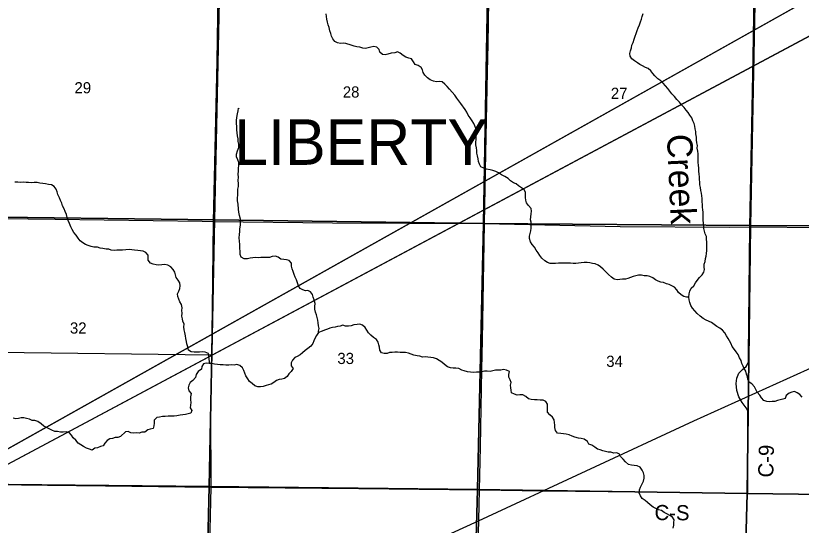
# Model space of a CAD drawing. Extents: x -6.2 to 37.4, y 0.2 to 22.2.
# Drawn here: x 3.568 to 5.038, y 18.286 to 19.239 of the extents above; entities that cross this region are included whole.
import ezdxf

# ---------------------------------------------------------------- set-up
doc = ezdxf.new("R2010")
doc.units = 0
for name, color, linetype in [('GM_X_County_Road', 7, 'Continuous'), ('GM_X_County_Road_Text', 7, 'Continuous'), ('GM_X_Minor_River', 7, 'Continuous'), ('GM_X_Minor_River_Text', 7, 'Continuous'), ('GM_X_Rail_Line', 7, 'Continuous'), ('GM_X_Section', 7, 'Continuous'), ('GM_X_Section_Text', 7, 'Continuous'), ('GM_X_Township_Road', 7, 'Continuous'), ('GM_X_Township_Text', 7, 'Continuous'), ('SH_Border', 7, 'Continuous'), ('SH_Data', 7, 'Continuous')]:
    doc.layers.add(name, color=color, linetype=linetype)

msp = doc.modelspace()

# ---------------------------------------------------------------- linework, layer by layer
at = {"layer": 'GM_X_County_Road'}
for points in [[(4.9421, 18.8443), (4.9484, 19.1615), (4.9514, 19.3541)], [(3.439, 18.8612), (3.6419, 18.8581), (3.9173, 18.8544), (3.9385, 18.8541), (4.161, 18.8513), (4.4458, 18.8505)], [(4.4458, 18.8505), (4.6995, 18.8444), (4.9048, 18.8435), (4.9421, 18.8443), (5.0809, 18.8428)], [(4.9381, 18.3459), (4.9384, 18.4907), (4.9383, 18.4998), (4.9352, 18.5053), (4.9276, 18.5153), (4.9215, 18.5262), (4.9174, 18.538), (4.9165, 18.5513), (4.9178, 18.5608), (4.9215, 18.5704), (4.9282, 18.5772), (4.9351, 18.5831), (4.9392, 18.5905), (4.9394, 18.6039), (4.9421, 18.8443)], [(3.4329, 18.3636), (3.6277, 18.3611), (3.7361, 18.3598), (3.9338, 18.3574), (4.2101, 18.3545), (4.4362, 18.3519), (4.4372, 18.3519)], [(4.4372, 18.3519), (4.5554, 18.3503), (4.7371, 18.3484), (4.9381, 18.3459), (4.9391, 18.3459)], [(4.9391, 18.3459), (5.0653, 18.3443), (5.0669, 18.3443), (5.0809, 18.3441)]]:
    msp.add_lwpolyline(points, dxfattribs=at)
at = {"layer": 'GM_X_Minor_River'}
for points in [[(4.4309, 18.9871), (4.4307, 18.9918), (4.4296, 18.9975), (4.429, 19.0023), (4.4299, 19.0076), (4.43, 19.0132), (4.4299, 19.0184), (4.4298, 19.0231), (4.4293, 19.0281), (4.4275, 19.0328), (4.4256, 19.0376), (4.4226, 19.0424), (4.4188, 19.0476), (4.4149, 19.0532), (4.4122, 19.0584), (4.4091, 19.0634), (4.401, 19.0745), (4.3975, 19.0795), (4.3936, 19.0849), (4.3901, 19.0903), (4.3853, 19.0959), (4.3802, 19.1015), (4.3757, 19.1063), (4.3715, 19.1111), (4.3661, 19.1151), (4.361, 19.1159), (4.3555, 19.1155), (4.35, 19.1163), (4.3436, 19.1187), (4.3386, 19.1228), (4.3336, 19.1275), (4.3308, 19.1326), (4.3298, 19.1374), (4.3267, 19.1422), (4.3211, 19.1457), (4.3158, 19.1474), (4.3127, 19.1529), (4.309, 19.1581), (4.304, 19.1595), (4.2983, 19.1616), (4.2931, 19.1645), (4.2879, 19.1688), (4.283, 19.1712), (4.2777, 19.1697), (4.271, 19.1687), (4.2649, 19.1672), (4.2594, 19.1659), (4.2545, 19.1664), (4.2495, 19.1707), (4.2485, 19.1755), (4.244, 19.1803), (4.2384, 19.1812), (4.2328, 19.1801), (4.2277, 19.1789), (4.2229, 19.1775), (4.2179, 19.1783), (4.2122, 19.18), (4.2066, 19.181), (4.2017, 19.1819), (4.1958, 19.1835), (4.186, 19.1868), (4.1811, 19.1874), (4.176, 19.1872), (4.1707, 19.1884), (4.1657, 19.1908), (4.1618, 19.1956), (4.1595, 19.2004), (4.1579, 19.2055), (4.1561, 19.2109), (4.1549, 19.2166), (4.1527, 19.2221), (4.1517, 19.2269), (4.1507, 19.2324), (4.15, 19.2376), (4.1495, 19.2425)], [(4.8611, 18.7944), (4.8616, 18.7997), (4.8618, 18.81), (4.8613, 18.8157), (4.8611, 18.8204), (4.8608, 18.8257), (4.8584, 18.8309), (4.857, 18.8357), (4.8562, 18.841), (4.8557, 18.8457), (4.8555, 18.8513), (4.8548, 18.8562), (4.8544, 18.8611), (4.8545, 18.8663), (4.8544, 18.8712), (4.8539, 18.8759), (4.8536, 18.8809), (4.8534, 18.886), (4.8525, 18.8909), (4.8526, 18.897), (4.852, 18.9018), (4.8513, 18.9069), (4.8505, 18.9118), (4.8497, 18.9176), (4.8483, 18.9229), (4.8482, 18.9276), (4.8479, 18.9324), (4.848, 18.9373), (4.8472, 18.9424), (4.8467, 18.9481), (4.8468, 18.9536), (4.846, 18.9595), (4.8454, 18.9645), (4.8451, 18.9698), (4.8453, 18.9804), (4.8445, 18.9854), (4.8434, 18.9909), (4.8439, 18.996), (4.8427, 19.0013), (4.8423, 19.0068), (4.842, 19.012), (4.8412, 19.0177), (4.8411, 19.0226), (4.8397, 19.0276), (4.8392, 19.0323), (4.8376, 19.0376), (4.8354, 19.0426), (4.8333, 19.0478), (4.8296, 19.0528), (4.8265, 19.0576), (4.8228, 19.0624), (4.8193, 19.0672), (4.8143, 19.0723), (4.8102, 19.0775), (4.8056, 19.0825), (4.8012, 19.0881), (4.7958, 19.0931), (4.7925, 19.0979), (4.7888, 19.1029), (4.784, 19.1076), (4.7799, 19.1126), (4.7753, 19.1174), (4.7701, 19.1209), (4.7645, 19.1262), (4.7606, 19.131), (4.757, 19.136), (4.7519, 19.1399), (4.7465, 19.1421), (4.7413, 19.1454), (4.7364, 19.1478), (4.7315, 19.1507), (4.7261, 19.1543), (4.7209, 19.1583), (4.718, 19.1633), (4.7175, 19.1683), (4.7188, 19.1734), (4.7204, 19.179), (4.7211, 19.1839), (4.7238, 19.1888), (4.7253, 19.1949), (4.7277, 19.2009), (4.7293, 19.2058), (4.7311, 19.2112), (4.7333, 19.2165), (4.7353, 19.222), (4.7373, 19.2276), (4.7393, 19.2325), (4.7407, 19.2376), (4.7422, 19.2431)], [(4.1352, 18.6462), (4.135, 18.6492), (4.1361, 18.6541), (4.1352, 18.6591), (4.1344, 18.6646), (4.1338, 18.6695), (4.1309, 18.6794), (4.1292, 18.6846), (4.128, 18.6903), (4.1281, 18.6951), (4.1286, 18.7007), (4.1268, 18.7074), (4.1252, 18.7127), (4.1234, 18.7175), (4.1201, 18.7223), (4.1152, 18.7251), (4.1105, 18.7246), (4.1056, 18.726), (4.1007, 18.7288), (4.0973, 18.734), (4.0953, 18.7391), (4.0935, 18.7447), (4.091, 18.75), (4.0894, 18.7548), (4.0876, 18.7603), (4.0854, 18.7657), (4.0844, 18.7706), (4.0843, 18.7763), (4.0801, 18.7812), (4.0752, 18.7824), (4.0699, 18.7829), (4.0646, 18.7839), (4.0594, 18.7876), (4.0545, 18.7891), (4.0482, 18.7886), (4.0433, 18.787), (4.0372, 18.7864), (4.0323, 18.7865), (4.0272, 18.7868), (4.0219, 18.7861), (4.017, 18.7864), (4.012, 18.7858), (4.0073, 18.7853), (4.002, 18.7844), (3.9961, 18.7844), (3.9899, 18.7873), (3.9885, 18.7921), (3.9886, 18.7982), (3.988, 18.8044), (3.988, 18.8111), (3.9873, 18.8174), (3.9863, 18.8238), (3.9872, 18.8297), (3.9879, 18.8354), (3.9874, 18.8403), (3.9887, 18.8471), (3.989, 18.8539), (3.989, 18.8587), (3.987, 18.8655), (3.986, 18.8716), (3.9852, 18.8773), (3.9846, 18.8866), (3.9836, 18.8929), (3.9833, 18.8978), (3.9837, 18.9041), (3.984, 18.9096), (3.9839, 18.9143), (3.9849, 18.9198), (3.9852, 18.9251), (3.9848, 18.9306), (3.9849, 18.9367), (3.9848, 18.9426), (3.9855, 18.948), (3.9855, 18.9535), (3.9859, 18.9587), (3.9857, 18.9642), (3.9841, 18.9691), (3.9817, 18.9747), (3.9815, 18.98), (3.9831, 18.9864), (3.9859, 18.9924), (3.9858, 18.9985), (3.9848, 19.0038), (3.9845, 19.0088), (3.9831, 19.0143), (3.9825, 19.02), (3.982, 19.0253), (3.982, 19.0316), (3.9817, 19.0374), (3.9816, 19.0428), (3.982, 19.0486), (3.9834, 19.0554), (3.9843, 19.0609), (3.9855, 19.0658), (3.9866, 19.0645)], [(4.8281, 18.7128), (4.8232, 18.7125), (4.8183, 18.7136), (4.8135, 18.7171), (4.8086, 18.7214), (4.8055, 18.7262), (4.8009, 18.731), (4.796, 18.7339), (4.7912, 18.7361), (4.7859, 18.7372), (4.7806, 18.7397), (4.7754, 18.7406), (4.7705, 18.7424), (4.7654, 18.7452), (4.7602, 18.7487), (4.7551, 18.7514), (4.7497, 18.7525), (4.7442, 18.7526), (4.7393, 18.7538), (4.7336, 18.7536), (4.7287, 18.7525), (4.7239, 18.7513), (4.7188, 18.7493), (4.714, 18.7472), (4.7092, 18.7461), (4.7039, 18.746), (4.6988, 18.7458), (4.6939, 18.7451), (4.6884, 18.7465), (4.6832, 18.7502), (4.6778, 18.7547), (4.6734, 18.7595), (4.6676, 18.7648), (4.6628, 18.7692), (4.6579, 18.7722), (4.6523, 18.7748), (4.6474, 18.7756), (4.6425, 18.777), (4.6374, 18.7775), (4.6317, 18.7776), (4.6262, 18.7768), (4.6213, 18.7761), (4.6165, 18.7757), (4.6112, 18.7758), (4.6063, 18.7761), (4.6014, 18.7762), (4.5952, 18.7763), (4.5897, 18.7762), (4.5842, 18.7759), (4.5783, 18.7757), (4.5736, 18.7752), (4.5686, 18.7753), (4.5634, 18.7773), (4.5582, 18.7804), (4.5531, 18.7853), (4.5491, 18.7903), (4.546, 18.7953), (4.5423, 18.8007), (4.5388, 18.8061), (4.5349, 18.8111), (4.5317, 18.8163), (4.5299, 18.822), (4.53, 18.8267), (4.531, 18.8316), (4.5323, 18.8367), (4.5326, 18.8416), (4.5329, 18.8468), (4.5326, 18.8525), (4.5318, 18.8572), (4.5319, 18.8625), (4.5327, 18.8684), (4.5332, 18.8733), (4.5329, 18.8782), (4.5276, 18.8842), (4.5239, 18.8892), (4.5229, 18.8942), (4.5224, 18.8989), (4.5223, 18.9037), (4.5222, 18.9086), (4.5199, 18.9134), (4.5145, 18.9169), (4.5094, 18.921), (4.5046, 18.9247), (4.4997, 18.9263), (4.4943, 18.9304), (4.4895, 18.9343), (4.4837, 18.938), (4.4775, 18.9416), (4.4719, 18.9449), (4.4665, 18.9477), (4.4612, 18.9495), (4.4559, 18.9509), (4.4495, 18.952), (4.4443, 18.9538), (4.4388, 18.9564), (4.4361, 18.9612), (4.4343, 18.9661), (4.4336, 18.9711), (4.4326, 18.9766), (4.431, 18.9817), (4.4309, 18.9871)], [(3.6086, 18.9272), (3.6031, 18.9269), (3.5984, 18.9262), (3.5925, 18.9267), (3.5876, 18.9268), (3.5825, 18.9273), (3.5774, 18.9268), (3.5725, 18.9273), (3.567, 18.9276)], [(3.9301, 18.5885), (3.9311, 18.5919), (3.9305, 18.597), (3.93, 18.6018), (3.9288, 18.6073), (3.923, 18.6095), (3.9175, 18.61), (3.9122, 18.6099), (3.9075, 18.6094), (3.9022, 18.6095), (3.8969, 18.61), (3.8915, 18.6137), (3.8901, 18.6194), (3.8887, 18.625), (3.8878, 18.6297), (3.8864, 18.6351), (3.886, 18.6404), (3.885, 18.6463), (3.8834, 18.6516), (3.8831, 18.6571), (3.8834, 18.6622), (3.8812, 18.6674), (3.8802, 18.6722), (3.8792, 18.6771), (3.8797, 18.6824), (3.8794, 18.6877), (3.8797, 18.6927), (3.8787, 18.6989), (3.8752, 18.7041), (3.8736, 18.7089), (3.8716, 18.7139), (3.8708, 18.7186), (3.8737, 18.7239), (3.8755, 18.7288), (3.8762, 18.7339), (3.8752, 18.7392), (3.8726, 18.7444), (3.8688, 18.7492), (3.8672, 18.7542), (3.8661, 18.7591), (3.8628, 18.7645), (3.8584, 18.7693), (3.8532, 18.7726), (3.8473, 18.7739), (3.8416, 18.7731), (3.8363, 18.7722), (3.831, 18.7727), (3.8256, 18.774), (3.8205, 18.7763), (3.8162, 18.7815), (3.8162, 18.7863), (3.8159, 18.791), (3.812, 18.7962), (3.807, 18.7986), (3.8019, 18.7991), (3.7966, 18.7998), (3.7905, 18.8006), (3.7856, 18.8011), (3.7805, 18.8018), (3.7741, 18.801), (3.7684, 18.8005), (3.7627, 18.8004), (3.7576, 18.8002), (3.7528, 18.7999), (3.7472, 18.8007), (3.7423, 18.8022), (3.7374, 18.8021), (3.7315, 18.8035), (3.7261, 18.8042), (3.7212, 18.806), (3.7147, 18.8063), (3.7095, 18.8074), (3.704, 18.809), (3.6991, 18.8108), (3.6939, 18.814), (3.6891, 18.8178), (3.6854, 18.823), (3.6815, 18.8284), (3.6769, 18.8334), (3.6742, 18.8388), (3.6716, 18.8438), (3.6687, 18.8503), (3.6664, 18.856), (3.6648, 18.8614), (3.6632, 18.8673), (3.6611, 18.8728), (3.6591, 18.878), (3.656, 18.8834), (3.6546, 18.8883), (3.6524, 18.8933), (3.6501, 18.8986), (3.6473, 18.9046), (3.6459, 18.9093), (3.6441, 18.9147), (3.6401, 18.9197), (3.635, 18.9227), (3.6298, 18.9235), (3.6243, 18.9242), (3.6188, 18.9254), (3.6137, 18.9257), (3.6086, 18.9272)], [(5.0396, 18.5254), (5.0354, 18.5302), (5.0303, 18.5335), (5.0253, 18.5363), (5.0203, 18.5349), (5.0155, 18.5329), (5.0101, 18.5286), (5.0083, 18.5228), (5.0036, 18.5215), (4.9986, 18.5205), (4.9939, 18.5193), (4.9889, 18.5173), (4.984, 18.5176), (4.9791, 18.5169), (4.9741, 18.5174), (4.9683, 18.5192), (4.9641, 18.5244), (4.9606, 18.5294), (4.956, 18.5346), (4.953, 18.5396), (4.9505, 18.5446), (4.9459, 18.5502), (4.941, 18.5537), (4.9381, 18.5587), (4.9374, 18.5636), (4.9357, 18.5686), (4.9344, 18.5739), (4.9315, 18.5789), (4.9294, 18.5837), (4.927, 18.5887), (4.9256, 18.594), (4.9225, 18.5992), (4.92, 18.605), (4.9165, 18.61), (4.9135, 18.6149), (4.9091, 18.62), (4.9068, 18.6253), (4.904, 18.6307), (4.9013, 18.6355), (4.8986, 18.6405), (4.8953, 18.6458), (4.8908, 18.6511), (4.886, 18.6548), (4.8804, 18.6579), (4.8753, 18.6612), (4.8701, 18.6653), (4.86, 18.6697), (4.8544, 18.6728), (4.8488, 18.6769), (4.8434, 18.682), (4.8391, 18.6868), (4.8349, 18.6922), (4.8316, 18.697), (4.8296, 18.7025), (4.8284, 18.7077), (4.8281, 18.7128), (4.8283, 18.7187), (4.8295, 18.7238), (4.8323, 18.7294), (4.8375, 18.734), (4.8406, 18.7391), (4.8436, 18.744), (4.8477, 18.7492), (4.8527, 18.754), (4.8562, 18.7593), (4.8571, 18.7642), (4.8568, 18.7689), (4.8567, 18.7744), (4.8585, 18.7793), (4.8588, 18.7846), (4.86, 18.7895), (4.8611, 18.7944)], [(4.3974, 18.5789), (4.3919, 18.5797), (4.3868, 18.5797), (4.3817, 18.5805), (4.3765, 18.5823), (4.3709, 18.5868), (4.3655, 18.5907), (4.3606, 18.5942), (4.3558, 18.597), (4.3501, 18.5992), (4.3452, 18.5995), (4.3394, 18.6002), (4.3345, 18.6008), (4.3295, 18.6005), (4.3246, 18.602), (4.3194, 18.603), (4.3133, 18.6039), (4.3083, 18.6061), (4.3034, 18.6079), (4.2977, 18.6088), (4.2928, 18.6091), (4.2877, 18.6092), (4.2828, 18.6094), (4.2779, 18.6099), (4.2727, 18.6093), (4.2678, 18.609), (4.2631, 18.6072), (4.2577, 18.6069), (4.2529, 18.6083), (4.2499, 18.6131), (4.2489, 18.6189), (4.2475, 18.6236), (4.2467, 18.6284), (4.2432, 18.6334), (4.2379, 18.6371), (4.2331, 18.6412), (4.2287, 18.646), (4.2252, 18.651), (4.2221, 18.6558), (4.2172, 18.6603), (4.2123, 18.6621), (4.2072, 18.6616), (4.201, 18.6606), (4.1958, 18.6588), (4.1909, 18.6583), (4.1856, 18.6581), (4.1803, 18.6599), (4.1755, 18.6584), (4.1706, 18.6574), (4.1659, 18.6564), (4.1611, 18.6555), (4.1563, 18.6543), (4.1516, 18.6529), (4.1464, 18.6509), (4.1415, 18.6491), (4.1352, 18.6462), (4.1309, 18.6411), (4.1289, 18.6363), (4.1263, 18.631), (4.1241, 18.6261), (4.1204, 18.6211), (4.1152, 18.6164), (4.1101, 18.6127), (4.1052, 18.6085), (4.1004, 18.6046), (4.0952, 18.6017), (4.0905, 18.6), (4.0862, 18.595), (4.0838, 18.5899), (4.0837, 18.5844), (4.0872, 18.5789), (4.0835, 18.5738), (4.0792, 18.569), (4.0761, 18.5639), (4.0713, 18.5602), (4.0664, 18.5594), (4.0612, 18.5585), (4.0564, 18.5564), (4.0515, 18.553), (4.0463, 18.5497), (4.0415, 18.5485), (4.0368, 18.5471), (4.0312, 18.5455), (4.0263, 18.545), (4.0212, 18.5451), (4.0157, 18.5468), (4.0109, 18.5512), (4.0061, 18.5547), (4.0026, 18.5601), (3.9991, 18.5657), (3.9951, 18.5752), (3.9926, 18.5804), (3.9878, 18.5847), (3.9823, 18.5865), (3.9768, 18.5855), (3.9719, 18.5857), (3.967, 18.5855), (3.9617, 18.5852), (3.9564, 18.5857), (3.9511, 18.586), (3.946, 18.5868)], [(3.946, 18.5868), (3.9401, 18.5873), (3.9352, 18.5882), (3.9301, 18.5885), (3.9245, 18.589), (3.9197, 18.5877), (3.9164, 18.5829), (3.9159, 18.578), (3.9099, 18.5733), (3.906, 18.5681), (3.9046, 18.5626), (3.8996, 18.5569), (3.8947, 18.553), (3.8924, 18.5477), (3.8909, 18.5428), (3.8921, 18.5375), (3.8964, 18.5321), (3.8951, 18.5259), (3.8952, 18.5207), (3.8959, 18.5158), (3.8952, 18.5107), (3.8947, 18.5056), (3.8976, 18.5004), (3.896, 18.4953), (3.8912, 18.4941), (3.8859, 18.4932), (3.881, 18.4924), (3.8762, 18.4917), (3.8698, 18.4905), (3.8647, 18.4899), (3.8595, 18.4898), (3.8537, 18.4897), (3.8482, 18.4896), (3.8429, 18.4894), (3.8374, 18.488), (3.8324, 18.4875), (3.8276, 18.4825), (3.8273, 18.477), (3.8268, 18.4719), (3.8257, 18.4668), (3.82, 18.4654), (3.8153, 18.4645), (3.8099, 18.4599), (3.8046, 18.46), (3.7993, 18.458), (3.794, 18.4589), (3.7892, 18.4584), (3.7839, 18.4591), (3.7789, 18.4615), (3.774, 18.4606), (3.7643, 18.4521), (3.7594, 18.4503), (3.7544, 18.4498), (3.7493, 18.4484), (3.7443, 18.4475), (3.7395, 18.4444), (3.7351, 18.4394), (3.732, 18.4345), (3.727, 18.4331), (3.7211, 18.4309), (3.7163, 18.4301), (3.7112, 18.4264), (3.7063, 18.428), (3.7008, 18.4304), (3.6954, 18.4334), (3.6905, 18.4363), (3.6855, 18.4394), (3.6809, 18.445), (3.6761, 18.4493), (3.6729, 18.4547), (3.6681, 18.4597), (3.6629, 18.4608), (3.6573, 18.4599), (3.6522, 18.4602), (3.6466, 18.4613), (3.6417, 18.4614), (3.6359, 18.464), (3.6308, 18.4665), (3.6259, 18.4687), (3.6207, 18.4713), (3.6157, 18.4754), (3.6095, 18.48), (3.6041, 18.4817), (3.5989, 18.482), (3.5939, 18.4841), (3.5886, 18.4854), (3.5837, 18.487), (3.5784, 18.4869), (3.5735, 18.4857), (3.5687, 18.485), (3.5636, 18.4863)], [(4.7972, 18.3008), (4.792, 18.3041), (4.7865, 18.3071), (4.7817, 18.3098), (4.7764, 18.3133), (4.7714, 18.3151), (4.7663, 18.3173), (4.7612, 18.3201), (4.7558, 18.3244), (4.7508, 18.3283), (4.746, 18.332), (4.7406, 18.3361), (4.7371, 18.3411), (4.7351, 18.3464), (4.7356, 18.3519), (4.7372, 18.3572), (4.7408, 18.3632), (4.7428, 18.3683), (4.7442, 18.3739), (4.7441, 18.3788), (4.7431, 18.3838), (4.7405, 18.389), (4.7365, 18.3944), (4.7309, 18.3969), (4.7254, 18.3978), (4.7203, 18.3985), (4.7148, 18.3997), (4.7095, 18.4046), (4.7052, 18.4098), (4.7002, 18.4148), (4.6978, 18.4198), (4.6928, 18.4214), (4.6875, 18.4209), (4.682, 18.4224), (4.6769, 18.4229), (4.6718, 18.4239), (4.6667, 18.4253), (4.6619, 18.4272), (4.6568, 18.4282), (4.6519, 18.4319), (4.6465, 18.4358), (4.6409, 18.4374), (4.6381, 18.4426), (4.6318, 18.4469), (4.6263, 18.4483), (4.6214, 18.449), (4.6145, 18.4507), (4.6096, 18.4525), (4.6038, 18.4549), (4.5985, 18.4561), (4.5883, 18.4575), (4.5821, 18.4583), (4.5782, 18.4634), (4.5772, 18.4685), (4.5771, 18.4732), (4.5766, 18.4782), (4.5756, 18.4833), (4.5728, 18.4881), (4.5678, 18.4922), (4.5634, 18.4976), (4.5633, 18.5025), (4.5635, 18.5122), (4.56, 18.5174), (4.555, 18.5198), (4.5497, 18.5197), (4.544, 18.5204), (4.5391, 18.5207), (4.5328, 18.521), (4.5278, 18.5222), (4.5226, 18.5267), (4.5175, 18.5296), (4.5115, 18.5299), (4.5067, 18.5293), (4.5014, 18.5311), (4.4962, 18.5335), (4.4952, 18.5384), (4.4945, 18.5432), (4.4944, 18.5479), (4.4951, 18.553), (4.4935, 18.5578), (4.4909, 18.563), (4.4909, 18.5677), (4.4921, 18.5734), (4.4869, 18.5759), (4.4808, 18.5774), (4.4761, 18.5763), (4.471, 18.5761), (4.466, 18.5758), (4.4611, 18.5749), (4.4562, 18.5735), (4.4505, 18.574), (4.4454, 18.5739), (4.4406, 18.5731), (4.4353, 18.5724), (4.4304, 18.572), (4.4251, 18.5717), (4.4192, 18.572), (4.4136, 18.5729), (4.4077, 18.5745), (4.4028, 18.5761), (4.3974, 18.5789)], [(4.7988, 18.2808), (4.7997, 18.2859), (4.7996, 18.2909), (4.8001, 18.296), (4.7972, 18.3008)]]:
    msp.add_lwpolyline(points, dxfattribs=at)
at = {"layer": 'GM_X_Rail_Line'}
msp.add_lwpolyline([(3.6937, 17.9569), (3.7272, 17.9723), (3.9289, 18.0637), (4.4341, 18.2944), (4.8371, 18.4811), (5.0692, 18.5857), (5.0809, 18.591)], dxfattribs=at)
at = {"layer": 'GM_X_Section'}
for points in [[(3.4485, 19.3634), (3.9512, 19.3544), (3.9401, 18.8573), (3.4402, 18.8631)], [(3.9512, 19.3544), (4.4522, 19.3499), (4.4434, 18.8501), (3.9401, 18.8573)], [(4.4522, 19.3499), (4.9531, 19.3564), (4.9435, 18.8467), (4.4434, 18.8501)], [(3.9401, 18.8573), (3.9301, 18.3582), (3.4289, 18.3634), (3.4402, 18.8631)], [(4.4434, 18.8501), (4.4323, 18.3529), (3.9301, 18.3582), (3.9401, 18.8573)], [(4.9435, 18.8467), (4.9367, 18.3451), (4.4323, 18.3529), (4.4434, 18.8501)], [(3.4289, 18.3634), (3.9301, 18.3582), (3.9187, 17.8532), (3.417, 17.8606)], [(3.9301, 18.3582), (4.4323, 18.3529), (4.419, 17.8503), (3.9187, 17.8532)], [(4.4323, 18.3529), (4.9367, 18.3451), (4.9235, 17.8453), (4.419, 17.8503)]]:
    msp.add_lwpolyline(points, close=True, dxfattribs=at)
for points in [[(5.0809, 18.8458), (4.9435, 18.8467), (4.9531, 19.3564), (5.0809, 19.3541)], [(5.0809, 18.3436), (4.9367, 18.3451), (4.9435, 18.8467), (5.0809, 18.8458)], [(5.0809, 17.8425), (4.9235, 17.8453), (4.9367, 18.3451), (5.0809, 18.3436)]]:
    msp.add_lwpolyline(points, dxfattribs=at)
at = {"layer": 'GM_X_Township_Road'}
for p, q in [((3.4355, 18.6108), (3.9352, 18.6044)), ((3.928, 18.1084), (3.9338, 18.3574))]:
    msp.add_line(p, q, dxfattribs=at)
for points in [[(4.4458, 18.8505), (4.4481, 18.9821), (4.4513, 19.134), (4.4523, 19.1854), (4.4549, 19.3499), (4.4556, 19.3926), (4.4577, 19.4978), (4.4606, 19.6355), (4.463, 19.7913), (4.4643, 19.8487)], [(3.9385, 18.8541), (3.9454, 19.1535), (3.9478, 19.3231), (3.9478, 19.3406), (3.9473, 19.3436), (3.9449, 19.3486)], [(3.9338, 18.3574), (3.9334, 18.4976), (3.9352, 18.6044), (3.9366, 18.691), (3.9385, 18.8541)], [(4.4362, 18.3519), (4.4378, 18.4325), (4.4408, 18.5775), (4.4418, 18.6322), (4.4458, 18.8505)], [(4.4249, 17.9094), (4.4251, 17.9146), (4.4295, 18.0929), (4.4309, 18.1466), (4.4349, 18.2952), (4.4362, 18.3519)]]:
    msp.add_lwpolyline(points, dxfattribs=at)
at = {"layer": 'SH_Border'}
for p, q in [((2.4803, 17.8272), (9.0866, 21.532)), ((9.0866, 21.3538), (2.4803, 17.8272))]:
    msp.add_line(p, q, dxfattribs=at)
at = {"layer": 'SH_Data'}
msp.add_lwpolyline([(9.0866, 21.3538), (2.4803, 17.8272), (9.0866, 21.532)], close=True, dxfattribs=at)

# ---------------------------------------------------------------- texts
at = {"layer": 'GM_X_County_Road_Text'}
for s, rotation, p in [('C-9', 88.6259, (4.9858, 18.375)), ('C-S', 359.5595, (4.7636, 18.2956))]:
    msp.add_text(s, height=0.02841, rotation=rotation, dxfattribs=at).set_placement(p)
at = {"layer": 'GM_X_Minor_River_Text'}
msp.add_text('Creek', height=0.04737, rotation=272.5896, dxfattribs=at).set_placement((4.7867, 19.0167))
at = {"layer": 'GM_X_Section_Text'}
for s, p in [('29', (3.6783, 19.0937)), ('28', (4.1804, 19.0858)), ('27', (4.6819, 19.0833)), ('32', (3.6698, 18.6444)), ('33', (4.1702, 18.5875)), ('34', (4.6733, 18.5821))]:
    msp.add_text(s, height=0.02093, rotation=0, dxfattribs=at).set_placement(p)
at = {"layer": 'GM_X_Township_Text'}
msp.add_text('LIBERTY', height=0.08523, rotation=0, dxfattribs=at).set_placement((3.9772, 18.96))

doc.saveas('drawing.dxf')
